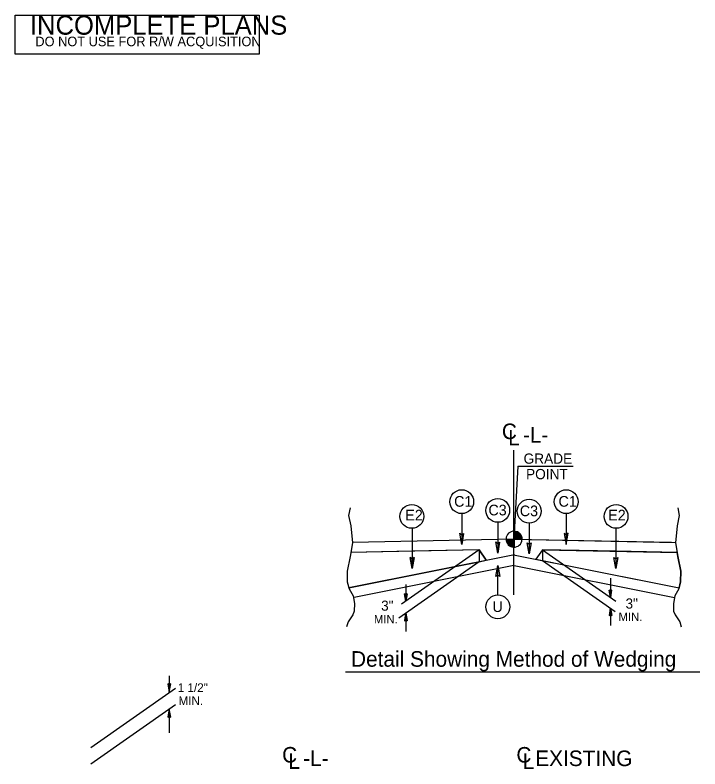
# Model space of a CAD drawing. Extents: x 1904401 to 1905163, y 193929 to 194736.
# Drawn here: x 1905067.5 to 1905150, y 194606.9 to 194697.6 of the extents above; entities that cross this region are included whole.
import ezdxf

# ---------------------------------------------------------------- set-up
doc = ezdxf.new("R2010")
doc.units = 0
for name, color, linetype in [('Old_Level_1', 7, 'Continuous'), ('Old_Level_11', 7, 'Continuous'), ('Old_Level_2', 7, 'Continuous'), ('Old_Level_20', 7, 'Continuous'), ('Old_Level_21', 7, 'Continuous'), ('Old_Level_3', 7, 'Continuous'), ('Prop Lane Arrow CELL', 7, 'Continuous'), ('Prop Shade Medium', 7, 'Continuous'), ('Sheet Sticker Incomplete CELL', 7, 'Continuous'), ('Typical Detail Wedge1 CELL', 7, 'Continuous')]:
    doc.layers.add(name, color=color, linetype=linetype)

msp = doc.modelspace()

# ---------------------------------------------------------------- linework, layer by layer
at = {"layer": 'Old_Level_1'}
for p, q in [((1905127.577, 194634.561), (1905127.577, 194635.518)), ((1905126.618, 194634.561), (1905127.577, 194634.561)), ((1905127.571, 194633.601), (1905127.571, 194634.549)), ((1905127.577, 194634.561), (1905127.577, 194633.601)), ((1905128.538, 194634.561), (1905127.577, 194634.561)), ((1905127.577, 194633.601), (1905127.577, 194634.561)), ((1905123.376, 194633.258), (1905114.034, 194626.716)), ((1905131.005, 194633.274), (1905139.841, 194627.085)), ((1905127.559, 194631.387), (1905108.317, 194627.538)), ((1905123.376, 194631.841), (1905113.718, 194625.044)), ((1905127.582, 194631.387), (1905146.897, 194627.523)), ((1905131.005, 194631.994), (1905139.755, 194625.868)), ((1905139.196, 194629.877), (1905139.196, 194627.538)), ((1905114.559, 194629.117), (1905114.559, 194627.083)), ((1905114.559, 194627.083), (1905114.401, 194627.978)), ((1905114.559, 194627.863), (1905114.401, 194627.978)), ((1905114.559, 194627.083), (1905114.423, 194627.962)), ((1905114.447, 194627.945), (1905114.559, 194627.083)), ((1905114.559, 194627.083), (1905114.47, 194627.929)), ((1905114.492, 194627.913), (1905114.559, 194627.083)), ((1905114.559, 194627.083), (1905114.514, 194627.896)), ((1905114.537, 194627.879), (1905114.559, 194627.083)), ((1905114.559, 194627.083), (1905114.717, 194627.978)), ((1905114.717, 194627.978), (1905114.559, 194627.863)), ((1905114.694, 194627.962), (1905114.559, 194627.083)), ((1905114.559, 194627.083), (1905114.672, 194627.945)), ((1905114.65, 194627.929), (1905114.559, 194627.083)), ((1905114.559, 194627.083), (1905114.627, 194627.913)), ((1905114.605, 194627.896), (1905114.559, 194627.083)), ((1905114.559, 194627.083), (1905114.582, 194627.879)), ((1905114.559, 194627.863), (1905114.559, 194627.083)), ((1905139.196, 194627.538), (1905139.039, 194628.433)), ((1905139.196, 194628.317), (1905139.039, 194628.433)), ((1905139.196, 194627.538), (1905139.06, 194628.416)), ((1905139.083, 194628.4), (1905139.196, 194627.538)), ((1905139.196, 194627.538), (1905139.106, 194628.383)), ((1905139.128, 194628.366), (1905139.196, 194627.538)), ((1905139.196, 194627.538), (1905139.15, 194628.35)), ((1905139.172, 194628.334), (1905139.196, 194627.538)), ((1905139.196, 194627.538), (1905139.354, 194628.433)), ((1905139.354, 194628.433), (1905139.196, 194628.317)), ((1905139.331, 194628.416), (1905139.196, 194627.538)), ((1905139.196, 194627.538), (1905139.308, 194628.4)), ((1905139.286, 194628.383), (1905139.196, 194627.538)), ((1905139.196, 194627.538), (1905139.263, 194628.366)), ((1905139.241, 194628.35), (1905139.196, 194627.538)), ((1905139.196, 194627.538), (1905139.219, 194628.334)), ((1905139.196, 194628.317), (1905139.196, 194627.538)), ((1905139.208, 194626.251), (1905139.05, 194625.355)), ((1905139.072, 194625.374), (1905139.208, 194626.251)), ((1905139.208, 194626.251), (1905139.094, 194625.389)), ((1905139.117, 194625.407), (1905139.208, 194626.251)), ((1905139.208, 194626.251), (1905139.14, 194625.423)), ((1905139.162, 194625.439), (1905139.208, 194626.251)), ((1905139.208, 194626.251), (1905139.184, 194625.455)), ((1905139.208, 194626.251), (1905139.208, 194624.158)), ((1905139.208, 194626.251), (1905139.366, 194625.355)), ((1905139.208, 194625.472), (1905139.208, 194626.251)), ((1905139.231, 194625.455), (1905139.208, 194626.251)), ((1905139.208, 194626.251), (1905139.252, 194625.439)), ((1905139.275, 194625.423), (1905139.208, 194626.251)), ((1905139.208, 194626.251), (1905139.297, 194625.407)), ((1905139.32, 194625.389), (1905139.208, 194626.251)), ((1905139.208, 194626.251), (1905139.342, 194625.374)), ((1905114.567, 194625.64), (1905114.408, 194624.745)), ((1905114.432, 194624.761), (1905114.567, 194625.64)), ((1905114.567, 194625.64), (1905114.455, 194624.778)), ((1905114.478, 194624.795), (1905114.567, 194625.64)), ((1905114.567, 194625.64), (1905114.5, 194624.812)), ((1905114.522, 194624.828), (1905114.567, 194625.64)), ((1905114.567, 194625.64), (1905114.544, 194624.843)), ((1905114.567, 194625.64), (1905114.567, 194623.464)), ((1905114.567, 194625.64), (1905114.725, 194624.745)), ((1905114.567, 194624.861), (1905114.567, 194625.64)), ((1905114.59, 194624.843), (1905114.567, 194625.64)), ((1905114.567, 194625.64), (1905114.613, 194624.828)), ((1905114.635, 194624.812), (1905114.567, 194625.64)), ((1905114.567, 194625.64), (1905114.657, 194624.795)), ((1905114.68, 194624.778), (1905114.567, 194625.64)), ((1905114.567, 194625.64), (1905114.702, 194624.761)), ((1905139.05, 194625.355), (1905139.208, 194625.472)), ((1905139.208, 194625.472), (1905139.366, 194625.355)), ((1905114.408, 194624.745), (1905114.567, 194624.861)), ((1905114.567, 194624.861), (1905114.725, 194624.745))]:
    msp.add_line(p, q, dxfattribs=at)
for points in [[(1905107.827, 194638.314), (1905107.665, 194637.422), (1905107.909, 194636.154), (1905108.124, 194634.102), (1905107.827, 194632.481), (1905107.477, 194630.726), (1905107.504, 194629.403), (1905107.72, 194628.566), (1905108.207, 194627.728), (1905108.368, 194626.81), (1905108.341, 194625.893), (1905108.179, 194625.46), (1905107.613, 194624.596), (1905107.424, 194624.001)], [(1905147.313, 194638.314), (1905147.475, 194637.422), (1905147.231, 194636.154), (1905147.016, 194634.102), (1905147.313, 194632.481), (1905147.664, 194630.726), (1905147.636, 194629.403), (1905147.42, 194628.566), (1905146.933, 194627.728), (1905146.772, 194626.81), (1905146.799, 194625.893), (1905146.961, 194625.46), (1905147.528, 194624.596), (1905147.717, 194624.001)], [(1905127.586, 194635.518), (1905127.586, 194635.518), (1905127.586, 194634.561)], [(1905127.605, 194635.518), (1905127.605, 194634.561)], [(1905127.625, 194635.518), (1905127.625, 194634.561)], [(1905127.644, 194635.517), (1905127.644, 194634.561)], [(1905127.664, 194635.516), (1905127.664, 194634.561)], [(1905127.682, 194635.513), (1905127.682, 194634.561)], [(1905127.703, 194635.512), (1905127.703, 194634.561)], [(1905127.72, 194635.508), (1905127.72, 194634.561)], [(1905127.74, 194635.505), (1905127.74, 194634.561)], [(1905127.759, 194635.501), (1905127.759, 194634.561)], [(1905127.779, 194635.499), (1905127.779, 194634.561)], [(1905127.799, 194635.494), (1905127.799, 194634.561)], [(1905127.818, 194635.489), (1905127.817, 194634.561)], [(1905127.836, 194635.484), (1905127.836, 194634.561)], [(1905127.854, 194635.478), (1905127.854, 194634.561)], [(1905127.873, 194635.472), (1905127.873, 194634.561)], [(1905127.894, 194635.465), (1905127.894, 194634.561)], [(1905127.913, 194635.459), (1905127.913, 194634.561)], [(1905127.932, 194635.451), (1905127.932, 194634.561)], [(1905127.952, 194635.444), (1905127.951, 194634.561)], [(1905127.971, 194635.435), (1905127.971, 194634.561)], [(1905127.989, 194635.427), (1905127.989, 194634.561)], [(1905128.008, 194635.417), (1905128.008, 194634.561)], [(1905128.028, 194635.407), (1905128.028, 194634.561)], [(1905128.047, 194635.395), (1905128.047, 194634.561)], [(1905128.067, 194635.384), (1905128.067, 194634.561)], [(1905128.086, 194635.373), (1905128.085, 194634.561)], [(1905128.105, 194635.362), (1905128.105, 194634.561)], [(1905128.123, 194635.349), (1905128.123, 194634.561)], [(1905128.142, 194635.334), (1905128.142, 194634.561)], [(1905128.163, 194635.32), (1905128.163, 194634.561)], [(1905128.181, 194635.305), (1905128.181, 194634.561)], [(1905128.202, 194635.289), (1905128.202, 194634.561)], [(1905128.22, 194635.273), (1905128.219, 194634.56)], [(1905128.24, 194635.254), (1905128.24, 194634.561)], [(1905128.257, 194635.236), (1905128.257, 194634.56)], [(1905128.277, 194635.216), (1905128.277, 194634.56)], [(1905128.297, 194635.193), (1905128.297, 194634.561)], [(1905128.315, 194635.172), (1905128.315, 194634.56)], [(1905128.336, 194635.148), (1905128.336, 194634.56)], [(1905128.355, 194635.124), (1905128.353, 194634.561)], [(1905128.374, 194635.097), (1905128.374, 194634.56)], [(1905128.391, 194635.065), (1905128.391, 194634.56)], [(1905128.411, 194635.034), (1905128.411, 194634.561)], [(1905128.431, 194634.998), (1905128.431, 194634.56)], [(1905128.45, 194634.958), (1905128.45, 194634.56)], [(1905128.47, 194634.914), (1905128.47, 194634.561)], [(1905126.623, 194634.561), (1905126.623, 194634.456)], [(1905126.643, 194634.561), (1905126.643, 194634.344)], [(1905126.663, 194634.561), (1905126.663, 194634.274)], [(1905126.682, 194634.561), (1905126.682, 194634.218)], [(1905126.7, 194634.561), (1905126.7, 194634.171)], [(1905126.719, 194634.561), (1905126.719, 194634.131)], [(1905126.738, 194634.561), (1905126.738, 194634.096)], [(1905126.758, 194634.561), (1905126.758, 194634.061)], [(1905126.777, 194634.561), (1905126.777, 194634.032)], [(1905126.797, 194634.561), (1905126.797, 194634.002)], [(1905126.816, 194634.561), (1905126.816, 194633.977)], [(1905126.835, 194634.561), (1905126.835, 194633.953)], [(1905126.853, 194634.561), (1905126.853, 194633.93)], [(1905126.872, 194634.561), (1905126.872, 194633.909)], [(1905126.892, 194634.561), (1905126.892, 194633.889)], [(1905126.911, 194634.561), (1905126.911, 194633.871)], [(1905126.932, 194634.561), (1905126.932, 194633.851)], [(1905126.95, 194634.561), (1905126.949, 194633.835)], [(1905126.968, 194634.561), (1905126.968, 194633.818)], [(1905126.987, 194634.561), (1905126.987, 194633.804)], [(1905127.007, 194634.561), (1905127.007, 194633.789)], [(1905127.027, 194634.561), (1905127.027, 194633.776)], [(1905127.046, 194634.561), (1905127.046, 194633.762)], [(1905127.066, 194634.561), (1905127.066, 194633.749)], [(1905127.084, 194634.561), (1905127.084, 194633.737)], [(1905127.103, 194634.561), (1905127.103, 194633.726)], [(1905127.122, 194634.561), (1905127.122, 194633.716)], [(1905127.141, 194634.561), (1905127.141, 194633.706)], [(1905127.16, 194634.561), (1905127.16, 194633.696)], [(1905127.18, 194634.561), (1905127.18, 194633.687)], [(1905127.2, 194634.561), (1905127.2, 194633.678)], [(1905127.219, 194634.561), (1905127.218, 194633.671)], [(1905127.237, 194634.561), (1905127.237, 194633.664)], [(1905127.257, 194634.561), (1905127.257, 194633.655)], [(1905127.275, 194634.561), (1905127.275, 194633.65)], [(1905127.295, 194634.561), (1905127.295, 194633.644)], [(1905127.314, 194634.561), (1905127.314, 194633.639)], [(1905127.334, 194634.561), (1905127.334, 194633.633)], [(1905127.354, 194634.561), (1905127.352, 194633.627)], [(1905127.371, 194634.561), (1905127.371, 194633.624)], [(1905127.392, 194634.561), (1905127.391, 194633.62)], [(1905127.409, 194634.561), (1905127.409, 194633.616)], [(1905127.429, 194634.561), (1905127.429, 194633.614)], [(1905127.448, 194634.561), (1905127.448, 194633.609)], [(1905127.469, 194634.561), (1905127.469, 194633.609)], [(1905127.487, 194634.561), (1905127.486, 194633.605)], [(1905127.505, 194634.561), (1905127.505, 194633.604)], [(1905127.526, 194634.561), (1905127.525, 194633.602)], [(1905127.544, 194634.561), (1905127.544, 194633.602)], [(1905127.564, 194634.561), (1905127.564, 194633.601), (1905127.564, 194633.601)], [(1905128.488, 194634.859), (1905128.488, 194634.56)], [(1905128.508, 194634.794), (1905128.508, 194634.56)], [(1905128.526, 194634.696), (1905128.526, 194634.561)]]:
    msp.add_lwpolyline(points, dxfattribs=at)
for start, end in [(358.00034, 356.17131), (359.99048, 89.99048), (179.99048, 268.71864), (269.65334, 269.99048)]:
    msp.add_arc((1905127.577, 194634.56), 0.959, start, end, dxfattribs=at)
at = {"layer": 'Old_Level_11'}
for p, q in [((1905127.57, 194627.847), (1905127.57, 194645.254)), ((1905121.278, 194637.635), (1905121.278, 194633.926)), ((1905133.863, 194637.635), (1905133.863, 194633.926)), ((1905115.302, 194635.868), (1905115.302, 194631.029)), ((1905125.616, 194636.591), (1905125.616, 194632.882)), ((1905129.398, 194636.491), (1905129.398, 194632.782)), ((1905139.838, 194635.868), (1905139.838, 194631.029)), ((1905127.57, 194634.561), (1905108.137, 194634.172)), ((1905127.57, 194634.561), (1905147.003, 194634.172)), ((1905127.573, 194634.561), (1905146.554, 194634.181)), ((1905123.376, 194633.258), (1905107.913, 194632.949)), ((1905123.376, 194633.258), (1905124.225, 194632.011)), ((1905123.376, 194633.258), (1905123.376, 194631.841)), ((1905131.005, 194633.274), (1905130.215, 194632.152)), ((1905131.005, 194633.274), (1905147.227, 194632.949)), ((1905131.005, 194633.274), (1905131.005, 194631.994)), ((1905127.617, 194632.69), (1905107.685, 194628.702)), ((1905127.526, 194632.69), (1905147.456, 194628.703)), ((1905125.623, 194627.843), (1905125.623, 194631.393)), ((1905107.293, 194618.595), (1905149.962, 194618.595))]:
    msp.add_line(p, q, dxfattribs=at)
for points in [[(1905121.507, 194635.255), (1905121.278, 194633.926), (1905121.041, 194635.262), (1905121.278, 194635.092)], [(1905133.633, 194635.255), (1905133.863, 194633.926), (1905134.099, 194635.262), (1905133.863, 194635.092)], [(1905125.845, 194634.211), (1905125.616, 194632.882), (1905125.38, 194634.218), (1905125.616, 194634.049)], [(1905129.627, 194634.111), (1905129.398, 194632.782), (1905129.162, 194634.118), (1905129.398, 194633.948)], [(1905115.073, 194632.358), (1905115.302, 194631.029), (1905115.538, 194632.365), (1905115.302, 194632.195)], [(1905140.067, 194632.358), (1905139.838, 194631.029), (1905139.602, 194632.365), (1905139.838, 194632.195)], [(1905125.394, 194630.064), (1905125.623, 194631.393), (1905125.86, 194630.057), (1905125.623, 194630.227)], [(1905085.894, 194617.151), (1905086.067, 194616.144), (1905086.246, 194617.156), (1905086.067, 194617.028)], [(1905086.24, 194613.141), (1905086.067, 194614.148), (1905085.888, 194613.136), (1905086.067, 194613.264)]]:
    msp.add_lwpolyline(points, close=True, dxfattribs=at)
for centre in [(1905121.278, 194639.07), (1905133.862, 194639.07), (1905125.616, 194638.026), (1905115.275, 194637.303), (1905129.398, 194637.926), (1905139.865, 194637.303), (1905125.623, 194626.408)]:
    msp.add_circle(centre, 1.435, dxfattribs=at)
at = {"layer": 'Old_Level_3'}
for q in [(1905127.573, 194634.56), (1905134.712, 194643.343)]:
    msp.add_line((1905128.042, 194643.343), q, dxfattribs=at)
at = {"layer": 'Prop Shade Medium'}
for p, q in [((1905124.225, 194632.011), (1905123.376, 194633.258)), ((1905131.005, 194633.274), (1905130.215, 194632.152)), ((1905130.215, 194632.152), (1905131.005, 194631.994)), ((1905107.685, 194628.702), (1905120.544, 194631.275)), ((1905120.544, 194631.275), (1905123.376, 194631.841)), ((1905123.376, 194631.841), (1905124.225, 194632.011)), ((1905131.005, 194631.994), (1905133.562, 194631.482)), ((1905133.562, 194631.482), (1905147.456, 194628.703)), ((1905147.456, 194628.703), (1905147.636, 194629.403))]:
    msp.add_line(p, q, dxfattribs=at)
for points in [[(1905123.376, 194633.258), (1905115.302, 194633.097), (1905107.913, 194632.949)], [(1905147.227, 194632.949), (1905139.838, 194633.097), (1905131.005, 194633.274)], [(1905107.913, 194632.949), (1905107.827, 194632.481), (1905107.477, 194630.726), (1905107.504, 194629.403), (1905107.685, 194628.702)], [(1905115.538, 194632.365), (1905115.302, 194631.029), (1905115.073, 194632.358), (1905115.302, 194632.195), (1905115.538, 194632.365)], [(1905140.067, 194632.358), (1905139.838, 194631.029), (1905139.602, 194632.365), (1905139.838, 194632.195), (1905140.067, 194632.358)], [(1905147.636, 194629.403), (1905147.664, 194630.726), (1905147.313, 194632.481), (1905147.227, 194632.949)]]:
    msp.add_lwpolyline(points, dxfattribs=at)
at = {"layer": 'Sheet Sticker Incomplete CELL'}
msp.add_lwpolyline([(1905067.497, 194692.935), (1905067.497, 194697.635), (1905096.897, 194697.635), (1905096.897, 194692.935)], close=True, dxfattribs=at)
at = {"layer": 'Typical Detail Wedge1 CELL'}
for p, q in [((1905086.067, 194618.119), (1905086.067, 194616.144)), ((1905076.622, 194609.475), (1905086.817, 194616.612)), ((1905076.622, 194607.534), (1905086.817, 194614.673)), ((1905086.067, 194614.148), (1905086.067, 194611.237))]:
    msp.add_line(p, q, dxfattribs=at)

# ---------------------------------------------------------------- texts
at = {"layer": 'Old_Level_11'}
for s, p in [('GRADE', (1905128.728, 194643.639)), ('POINT', (1905129.025, 194641.775))]:
    msp.add_text(s, height=1.23, dxfattribs=at).set_placement(p)
at = {"layer": 'Old_Level_2'}
for p in [(1905126.114, 194646.597), (1905099.654, 194607.67), (1905127.862, 194607.664)]:
    msp.add_text('C', height=1.875, dxfattribs=at).set_placement(p)
for s, p in [('L', (1905126.868, 194645.839)), ('-L-', (1905128.647, 194646.182)), ('L', (1905100.407, 194606.912)), ('-L-', (1905102.186, 194607.255)), ('L', (1905128.616, 194606.906)), ('EXISTING', (1905130.128, 194607.252))]:
    msp.add_text(s, height=1.875, rotation=359.9469, dxfattribs=at).set_placement(p)
at = {"layer": 'Old_Level_20'}
for s, height, p in [('C1', 1.2846, (1905120.365, 194638.464)), ('C1', 1.2846, (1905132.934, 194638.464)), ('C3', 1.2846, (1905124.495, 194637.42)), ('C3', 1.2846, (1905128.277, 194637.32)), ('E2', 1.2846, (1905114.484, 194636.809)), ('E2', 1.2846, (1905138.921, 194636.809)), ('3"', 1.2171, (1905111.579, 194625.946)), ('U', 1.285, (1905124.981, 194625.791)), ('3"', 1.2171, (1905141.008, 194626.205))]:
    msp.add_text(s, height=height, dxfattribs=at).set_placement(p)
at = {"layer": 'Old_Level_21'}
for s, height, p in [('MIN.', 1.017, (1905110.707, 194624.414)), ('MIN.', 1.017, (1905140.161, 194624.707)), ('Detail Showing Method of Wedging', 1.875, (1905107.95, 194619.203))]:
    msp.add_text(s, height=height, dxfattribs=at).set_placement(p)
at = {"layer": 'Prop Lane Arrow CELL'}
for s, p in [('1 1/2"', (1905087.086, 194616.158)), ('MIN.', (1905087.186, 194614.583))]:
    msp.add_text(s, height=1.05, rotation=360, dxfattribs=at).set_placement(p)
at = {"layer": 'Sheet Sticker Incomplete CELL'}
for s, height, p in [('INCOMPLETE PLANS', 2.304, (1905069.287, 194695.275)), ('DO NOT USE FOR R/W ACQUISITION', 1.152, (1905069.937, 194693.885))]:
    msp.add_text(s, height=height, dxfattribs=at).set_placement(p)

doc.saveas('drawing.dxf')
